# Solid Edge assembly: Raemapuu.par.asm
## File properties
Author: Kasutaja
Template: iso metric assembly.asm
Last saved by: Kasutaja
Revision: 22
Application: Solid Edge
Username: Kasutaja
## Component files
kilp2_mir.psm
aer.par
aer_mir2.par
Raemapuu.par
ramast.par
spirdipulgad.par
puri ja lipp.par
spirt.par
parras_mir.par
parras.par
kirst.par
vedru.par
kilp2.psm
tekk.par
r.par
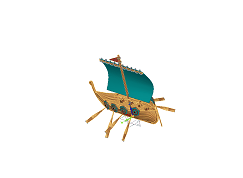
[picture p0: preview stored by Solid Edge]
